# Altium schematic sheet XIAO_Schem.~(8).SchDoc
size A; SheetNumber: 1; SheetTotal: 1
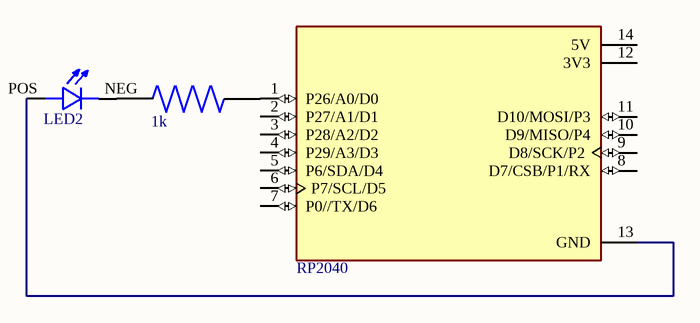
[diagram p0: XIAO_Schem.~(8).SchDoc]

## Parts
1k  1k  [1k]  (value not drawn)
LED2  LHN974_RED_LED_1206  [LED2]  (value not drawn)
RP2040  102010428  [102010428]  (value not drawn)

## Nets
Net1k_1: 1k.1 LED2.NEG
Net1k_2: 1k.2 RP2040.1(P26/A0/D0)
NetLED2_POS: LED2.POS RP2040.13(GND)

Not connected (* = marked no-connect by the designer): RP2040 2(P27/A1/D1) 3(P28/A2/D2) 4(P29/A3/D3) 5(P6/SDA/D4) 6(P7/SCL/D5) 7(P0//TX/D6) 8(D7/CSB/P1/RX) 9(D8/SCK/P2) 10(D9/MISO/P4) 11(D10/MOSI/P3) 12(3V3) 14(5V)

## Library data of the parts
1k = 1k: Res Thick Film 3.2 x 1.6 mm 6.8K Ohm 1% 0.25W(1/4W) 100ppm/ C Molded SMD Paper T/R; MP: RC1206FR-076K8L
LED2 = LED2: 2.6 V Red LED SMD; MP: LHN974 RED LED 1206; MF: Osram
RP2040 = 102010428: RP2040 XIAO RP2040 series ARMÂ® CortexÂ®-M0+ MCU 32-Bit Embedded Evaluation Board; MF: Seeed Technology Co., Ltd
